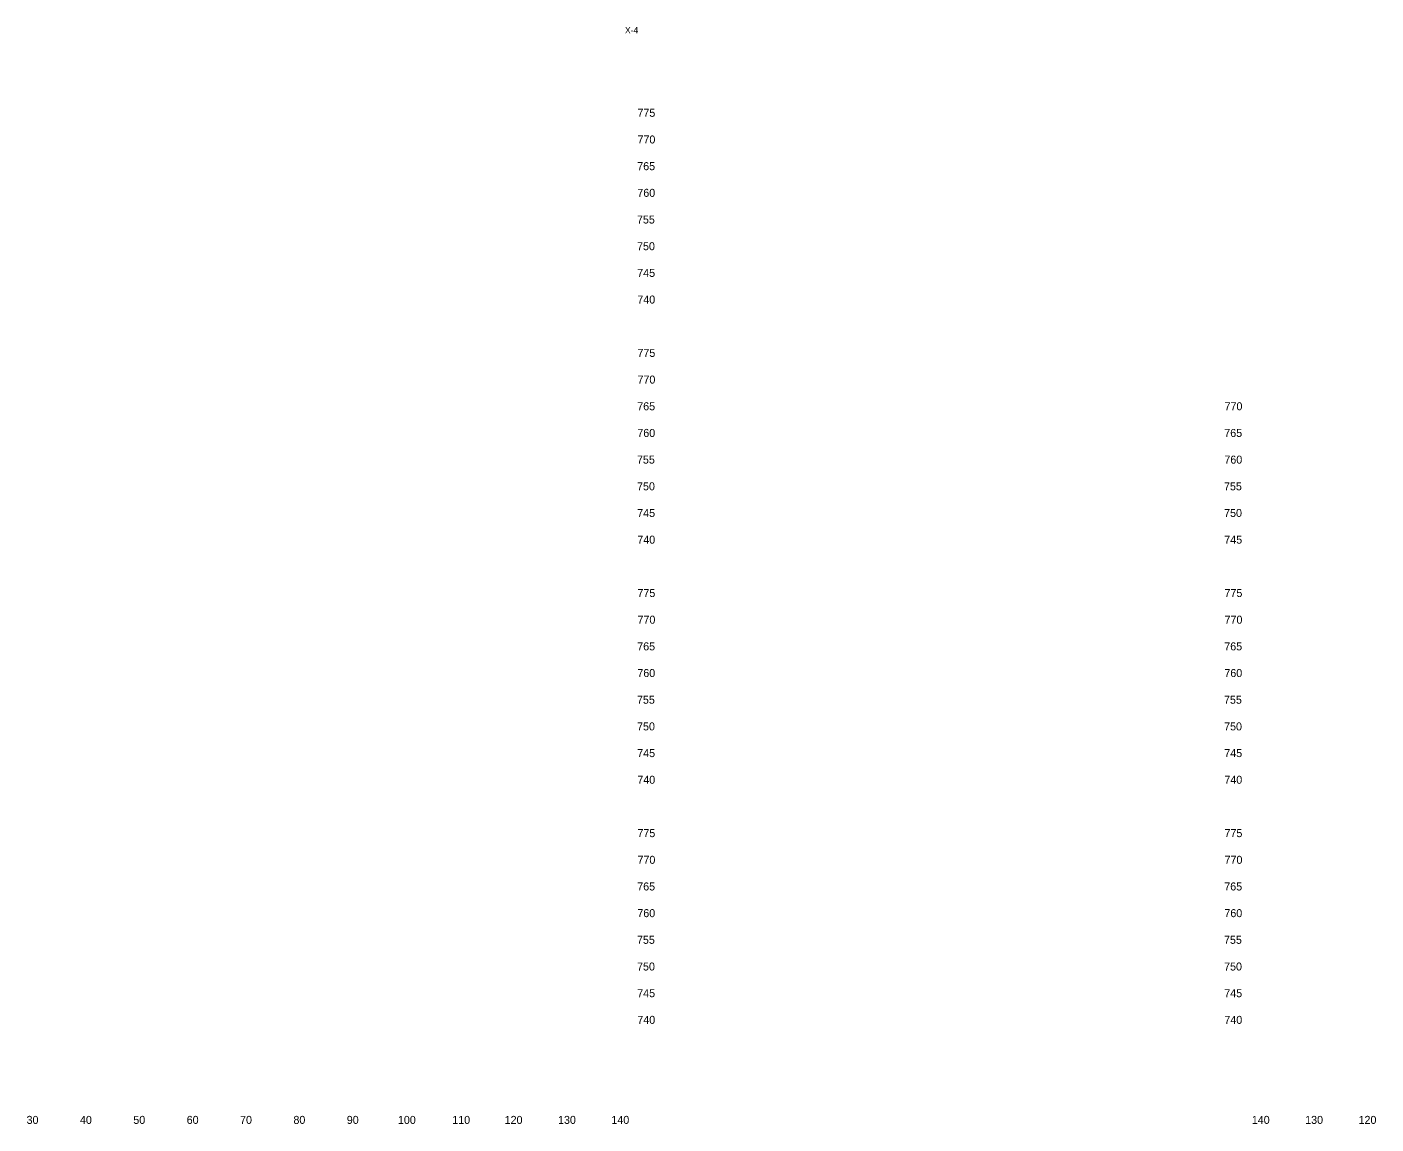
# Model space of a CAD drawing. Extents: x 2473106 to 2475402, y 633617 to 633851.
# Drawn here: x 2474884.6 to 2475137.4, y 633618.8 to 633824.4 of the extents above; entities that cross this region are included whole.
import ezdxf

# ---------------------------------------------------------------- set-up
doc = ezdxf.new("R2010")
doc.units = 0
for name, color, linetype in [('Exist Cross Section Cell', 7, 'Continuous'), ('Exist XS Ground Line', 7, 'Continuous'), ('Prop XS SE Text', 7, 'Continuous')]:
    doc.layers.add(name, color=color, linetype=linetype)

msp = doc.modelspace()

# ---------------------------------------------------------------- texts
at = {"layer": 'Exist Cross Section Cell'}
for s, p in [('30', (2474884.55, 633618.82)), ('40', (2474894.55, 633618.82)), ('50', (2474904.55, 633618.82)), ('60', (2474914.55, 633618.82)), ('70', (2474924.55, 633618.82)), ('80', (2474934.55, 633618.82)), ('90', (2474944.55, 633618.82)), ('100', (2474954.13, 633618.82)), ('110', (2474964.31, 633618.82)), ('120', (2474974.13, 633618.82)), ('130', (2474984.13, 633618.82)), ('140', (2474994.13, 633618.82)), ('140', (2475114.13, 633618.82)), ('130', (2475124.13, 633618.82)), ('120', (2475134.13, 633618.82))]:
    msp.add_text(s, height=1.5, dxfattribs=at).set_placement(p)
at = {"layer": 'Exist XS Ground Line'}
for s, p in [('775', (2474999.01, 633807.57)), ('770', (2474999.02, 633802.57)), ('765', (2474998.97, 633797.57)), ('760', (2474998.99, 633792.57)), ('755', (2474998.92, 633787.57)), ('750', (2474998.94, 633782.57)), ('745', (2474998.97, 633777.57)), ('740', (2474998.99, 633772.57)), ('775', (2474999.01, 633762.57)), ('770', (2474999.02, 633757.57)), ('765', (2474998.97, 633752.57)), ('770', (2475109.02, 633752.57)), ('760', (2474998.99, 633747.57)), ('765', (2475108.97, 633747.57)), ('755', (2474998.92, 633742.57)), ('760', (2475108.99, 633742.57)), ('750', (2474998.94, 633737.57)), ('755', (2475108.92, 633737.57)), ('745', (2474998.97, 633732.57)), ('750', (2475108.94, 633732.57)), ('740', (2474998.99, 633727.57)), ('745', (2475108.97, 633727.57)), ('775', (2474999.01, 633717.57)), ('775', (2475109.01, 633717.57)), ('770', (2474999.02, 633712.57)), ('770', (2475109.02, 633712.57)), ('765', (2474998.97, 633707.57)), ('765', (2475108.97, 633707.57)), ('760', (2474998.99, 633702.57)), ('760', (2475108.99, 633702.57)), ('755', (2474998.92, 633697.57)), ('755', (2475108.92, 633697.57)), ('750', (2474998.94, 633692.57)), ('750', (2475108.94, 633692.57)), ('745', (2474998.97, 633687.57)), ('745', (2475108.97, 633687.57)), ('740', (2474998.99, 633682.57)), ('740', (2475108.99, 633682.57)), ('775', (2474999.01, 633672.57)), ('775', (2475109.01, 633672.57)), ('770', (2474999.02, 633667.57)), ('770', (2475109.02, 633667.57)), ('765', (2474998.97, 633662.57)), ('765', (2475108.97, 633662.57)), ('760', (2474998.99, 633657.57)), ('760', (2475108.99, 633657.57)), ('755', (2474998.92, 633652.57)), ('755', (2475108.92, 633652.57)), ('750', (2474998.94, 633647.57)), ('750', (2475108.94, 633647.57)), ('745', (2474998.97, 633642.57)), ('745', (2475108.97, 633642.57)), ('740', (2474998.99, 633637.57)), ('740', (2475108.99, 633637.57))]:
    msp.add_text(s, height=1.5, dxfattribs=at).set_placement(p)
at = {"layer": 'Prop XS SE Text'}
msp.add_text('X-4', height=1.2, dxfattribs=at).set_placement((2474996.67, 633823.21))

doc.saveas('drawing.dxf')
